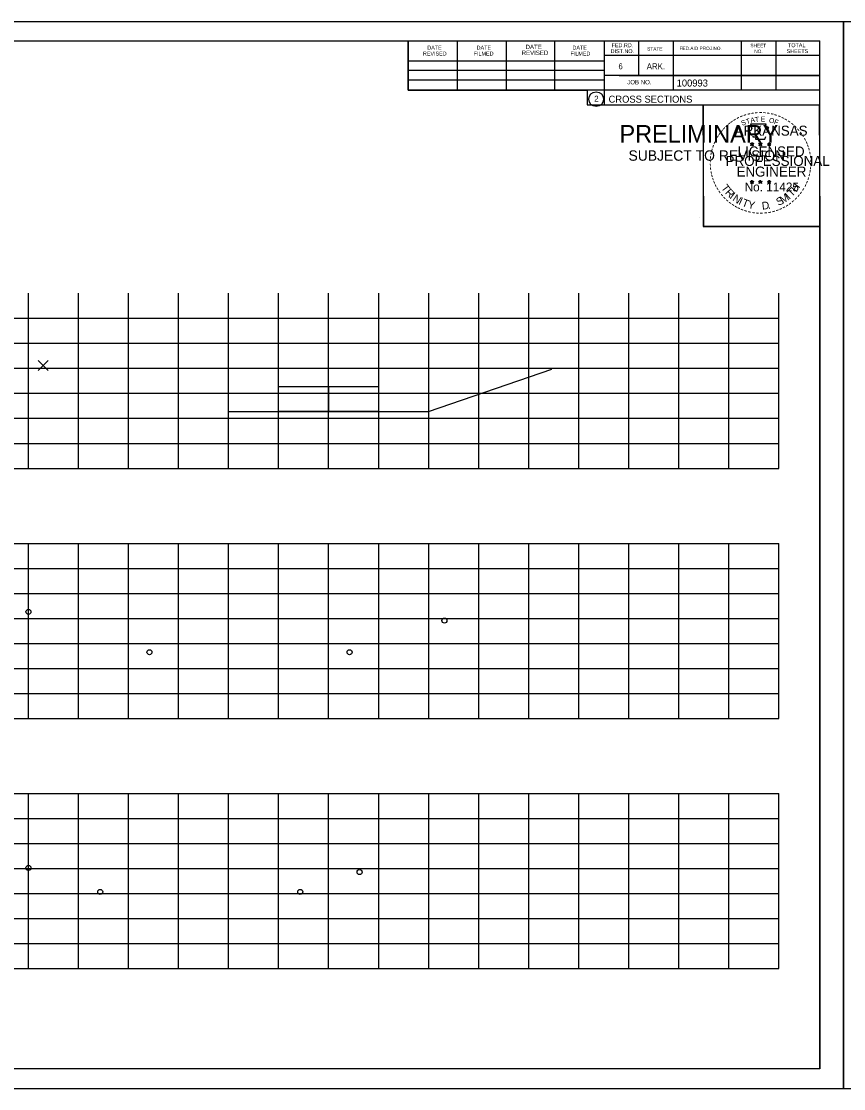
# Model space of a CAD drawing. Extents: x 4667 to 1632277, y -2100 to 724501.
# Drawn here: x 6138.1 to 6302.5, y -1750.4 to -1537.1 of the extents above; entities that cross this region are included whole.
import ezdxf

# ---------------------------------------------------------------- set-up
doc = ezdxf.new("R2010")
doc.units = 0
for name, color, linetype in [('R_Grid', 7, 'Continuous'), ('R_No Plot', 7, 'Continuous'), ('R_Water', 7, 'Continuous')]:
    doc.layers.add(name, color=color, linetype=linetype)

msp = doc.modelspace()

# ---------------------------------------------------------------- linework, layer by layer
at = {"layer": 'R_Grid'}
for p, q in [((6139.52, -1626.44), (6139.52, -1591.44)), ((6149.52, -1626.44), (6149.52, -1591.44)), ((6159.52, -1626.44), (6159.52, -1591.44)), ((6169.52, -1626.44), (6169.52, -1591.44)), ((6179.52, -1626.44), (6179.52, -1591.44)), ((6189.52, -1626.44), (6189.52, -1591.44)), ((6199.52, -1626.44), (6199.52, -1591.44)), ((6209.52, -1626.44), (6209.52, -1591.44)), ((6219.52, -1626.44), (6219.52, -1591.44)), ((6229.52, -1626.44), (6229.52, -1591.44)), ((6239.52, -1626.44), (6239.52, -1591.44)), ((6249.52, -1626.44), (6249.52, -1591.44)), ((6259.52, -1626.44), (6259.52, -1591.44)), ((6269.52, -1626.44), (6269.52, -1591.44)), ((6279.52, -1626.44), (6279.52, -1591.44)), ((6289.52, -1626.44), (6289.52, -1591.44)), ((5989.52, -1596.44), (6289.52, -1596.44)), ((5989.52, -1601.44), (6289.52, -1601.44)), ((5989.52, -1606.44), (6289.52, -1606.44)), ((5989.52, -1611.44), (6289.52, -1611.44)), ((5989.52, -1616.44), (6289.52, -1616.44)), ((5989.52, -1621.44), (6289.52, -1621.44)), ((5989.52, -1626.44), (6289.52, -1626.44)), ((5989.52, -1641.44), (6289.52, -1641.44)), ((6139.52, -1676.44), (6139.52, -1641.44)), ((6149.52, -1676.44), (6149.52, -1641.44)), ((6159.52, -1676.44), (6159.52, -1641.44)), ((6169.52, -1676.44), (6169.52, -1641.44)), ((6179.52, -1676.44), (6179.52, -1641.44)), ((6189.52, -1676.44), (6189.52, -1641.44)), ((6199.52, -1676.44), (6199.52, -1641.44)), ((6209.52, -1676.44), (6209.52, -1641.44)), ((6219.52, -1676.44), (6219.52, -1641.44)), ((6229.52, -1676.44), (6229.52, -1641.44)), ((6239.52, -1676.44), (6239.52, -1641.44)), ((6249.52, -1676.44), (6249.52, -1641.44)), ((6259.52, -1676.44), (6259.52, -1641.44)), ((6269.52, -1676.44), (6269.52, -1641.44)), ((6279.52, -1676.44), (6279.52, -1641.44)), ((6289.52, -1676.44), (6289.52, -1641.44)), ((5989.52, -1646.44), (6289.52, -1646.44)), ((5989.52, -1651.44), (6289.52, -1651.44)), ((5989.52, -1656.44), (6289.52, -1656.44)), ((5989.52, -1661.44), (6289.52, -1661.44)), ((5989.52, -1666.44), (6289.52, -1666.44)), ((5989.52, -1671.44), (6289.52, -1671.44)), ((5989.52, -1676.44), (6289.52, -1676.44)), ((5989.52, -1691.44), (6289.52, -1691.44)), ((6139.52, -1726.44), (6139.52, -1691.44)), ((6149.52, -1726.44), (6149.52, -1691.44)), ((6159.52, -1726.44), (6159.52, -1691.44)), ((6169.52, -1726.44), (6169.52, -1691.44)), ((6179.52, -1726.44), (6179.52, -1691.44)), ((6189.52, -1726.44), (6189.52, -1691.44)), ((6199.52, -1726.44), (6199.52, -1691.44)), ((6209.52, -1726.44), (6209.52, -1691.44)), ((6219.52, -1726.44), (6219.52, -1691.44)), ((6229.52, -1726.44), (6229.52, -1691.44)), ((6239.52, -1726.44), (6239.52, -1691.44)), ((6249.52, -1726.44), (6249.52, -1691.44)), ((6259.52, -1726.44), (6259.52, -1691.44)), ((6269.52, -1726.44), (6269.52, -1691.44)), ((6279.52, -1726.44), (6279.52, -1691.44)), ((6289.52, -1726.44), (6289.52, -1691.44)), ((5989.52, -1696.44), (6289.52, -1696.44)), ((5989.52, -1701.44), (6289.52, -1701.44)), ((5989.52, -1706.44), (6289.52, -1706.44)), ((5989.52, -1711.44), (6289.52, -1711.44)), ((5989.52, -1716.44), (6289.52, -1716.44)), ((5989.52, -1721.44), (6289.52, -1721.44)), ((5989.52, -1726.44), (6289.52, -1726.44))]:
    msp.add_line(p, q, dxfattribs=at)
at = {"layer": 'R_No Plot'}
for p, q in [((5969.12, -1537.09), (6302.46, -1537.09)), ((5981.52, -1540.98), (6297.7, -1540.98)), ((6215.44, -1550.86), (6215.44, -1540.98)), ((6225.3, -1550.86), (6225.3, -1541.18)), ((6235.06, -1550.86), (6235.06, -1541.18)), ((6244.74, -1550.86), (6244.74, -1541.18)), ((6254.6, -1540.98), (6254.6, -1553.78)), ((6261.44, -1540.98), (6261.44, -1547.92)), ((6268.38, -1540.98), (6268.38, -1550.86)), ((6281.96, -1540.98), (6281.96, -1550.86)), ((6288.9, -1540.98), (6288.9, -1550.86)), ((6297.7, -1746.44), (6297.7, -1540.98)), ((6297.7, -1543.92), (6254.6, -1543.92)), ((6297.7, -1543.9), (6297.7, -1543.9)), ((6215.44, -1545), (6254.6, -1545)), ((6215.44, -1546.86), (6254.6, -1546.86)), ((6215.44, -1550.86), (6215.44, -1548.8)), ((6215.44, -1548.8), (6254.6, -1548.8)), ((6297.7, -1547.92), (6254.6, -1547.92)), ((6257.56, -1547.92), (6297.7, -1547.92)), ((6297.7, -1550.86), (6215.44, -1550.86)), ((6254.6, -1553.78), (6297.7, -1553.78)), ((6283.79, -1561.53), (6284.14, -1561.64)), ((6283.79, -1561.53), (6284.04, -1561.57)), ((6283.79, -1561.53), (6284.03, -1561.65)), ((6284.14, -1561.28), (6284.1, -1561.53)), ((6284.14, -1561.64), (6284.14, -1561.28)), ((6284.14, -1561.28), (6284.19, -1561.53)), ((6284.49, -1561.53), (6284.14, -1561.64)), ((6284.49, -1561.53), (6284.2, -1561.58)), ((6284.49, -1561.53), (6284.28, -1561.63)), ((6285.46, -1561.53), (6285.81, -1561.64)), ((6285.46, -1561.53), (6285.71, -1561.57)), ((6285.46, -1561.53), (6285.7, -1561.65)), ((6285.81, -1561.28), (6285.77, -1561.53)), ((6285.81, -1561.64), (6285.81, -1561.28)), ((6285.81, -1561.28), (6285.86, -1561.53)), ((6286.16, -1561.53), (6285.81, -1561.64)), ((6286.16, -1561.53), (6285.87, -1561.58)), ((6286.16, -1561.53), (6285.95, -1561.63)), ((6287.22, -1561.54), (6287.57, -1561.65)), ((6287.22, -1561.54), (6287.48, -1561.59)), ((6287.22, -1561.54), (6287.46, -1561.66)), ((6287.57, -1561.29), (6287.53, -1561.54)), ((6287.57, -1561.65), (6287.57, -1561.29)), ((6287.57, -1561.29), (6287.62, -1561.54)), ((6287.92, -1561.54), (6287.57, -1561.65)), ((6287.92, -1561.54), (6287.63, -1561.59)), ((6287.92, -1561.54), (6287.72, -1561.64)), ((6283.92, -1561.94), (6284.14, -1561.64)), ((6283.92, -1561.94), (6284.05, -1561.69)), ((6283.92, -1561.94), (6284.14, -1561.72)), ((6284.35, -1561.94), (6284.14, -1561.64)), ((6284.35, -1561.94), (6284.14, -1561.72)), ((6284.35, -1561.94), (6284.21, -1561.65)), ((6285.59, -1561.94), (6285.81, -1561.64)), ((6285.59, -1561.94), (6285.72, -1561.69)), ((6285.59, -1561.94), (6285.81, -1561.72)), ((6286.02, -1561.94), (6285.81, -1561.64)), ((6286.02, -1561.94), (6285.81, -1561.72)), ((6286.02, -1561.94), (6285.88, -1561.65)), ((6287.36, -1561.95), (6287.57, -1561.65)), ((6287.36, -1561.95), (6287.48, -1561.71)), ((6287.36, -1561.95), (6287.57, -1561.73)), ((6287.79, -1561.95), (6287.57, -1561.65)), ((6287.79, -1561.95), (6287.57, -1561.74)), ((6287.79, -1561.95), (6287.65, -1561.66)), ((6283.79, -1569.1), (6284.13, -1569.21)), ((6283.79, -1569.1), (6284.04, -1569.15)), ((6283.79, -1569.1), (6284.02, -1569.22)), ((6283.92, -1569.51), (6284.13, -1569.21)), ((6283.92, -1569.51), (6284.04, -1569.27)), ((6283.92, -1569.51), (6284.13, -1569.29)), ((6284.13, -1568.85), (6284.09, -1569.1)), ((6284.13, -1569.21), (6284.13, -1568.85)), ((6284.13, -1568.85), (6284.18, -1569.1)), ((6284.48, -1569.1), (6284.13, -1569.21)), ((6284.35, -1569.51), (6284.13, -1569.21)), ((6284.35, -1569.51), (6284.13, -1569.3)), ((6284.48, -1569.1), (6284.2, -1569.15)), ((6284.35, -1569.51), (6284.21, -1569.22)), ((6284.48, -1569.1), (6284.28, -1569.2)), ((6285.45, -1569.1), (6285.8, -1569.21)), ((6285.45, -1569.1), (6285.71, -1569.15)), ((6285.45, -1569.1), (6285.69, -1569.22)), ((6285.59, -1569.51), (6285.8, -1569.21)), ((6285.59, -1569.51), (6285.71, -1569.27)), ((6285.59, -1569.51), (6285.8, -1569.29)), ((6285.8, -1568.85), (6285.76, -1569.1)), ((6285.8, -1569.21), (6285.8, -1568.85)), ((6285.8, -1568.85), (6285.85, -1569.1)), ((6286.15, -1569.1), (6285.8, -1569.21)), ((6286.02, -1569.51), (6285.8, -1569.21)), ((6286.02, -1569.51), (6285.8, -1569.3)), ((6286.15, -1569.1), (6285.86, -1569.15)), ((6286.02, -1569.51), (6285.88, -1569.22)), ((6286.15, -1569.1), (6285.95, -1569.2)), ((6287.22, -1569.11), (6287.57, -1569.22)), ((6287.22, -1569.11), (6287.47, -1569.16)), ((6287.22, -1569.11), (6287.46, -1569.23)), ((6287.35, -1569.52), (6287.57, -1569.22)), ((6287.35, -1569.52), (6287.48, -1569.28)), ((6287.35, -1569.52), (6287.57, -1569.3)), ((6287.57, -1568.86), (6287.53, -1569.11)), ((6287.57, -1569.22), (6287.57, -1568.86)), ((6287.57, -1568.86), (6287.62, -1569.11)), ((6287.92, -1569.11), (6287.57, -1569.22)), ((6287.78, -1569.52), (6287.57, -1569.22)), ((6287.78, -1569.52), (6287.57, -1569.31)), ((6287.92, -1569.11), (6287.63, -1569.16)), ((6287.78, -1569.52), (6287.65, -1569.23)), ((6287.92, -1569.11), (6287.71, -1569.21)), ((6273.74, -1576.24), (6273.74, -1576.24)), ((6297.7, -1746.44), (5981.52, -1746.44)), ((5969.12, -1750.42), (6302.46, -1750.42))]:
    msp.add_line(p, q, dxfattribs=at)
for points in [[(5969.12, -1537.09), (6302.46, -1537.09), (6302.46, -1750.43), (5969.12, -1750.43)], [(6302.46, -1537.09), (6635.8, -1537.09), (6635.8, -1750.43), (6302.46, -1750.43)], [(6215.44, -1540.98), (6215.44, -1550.86), (6251.18, -1550.86), (6251.18, -1553.78), (6274.38, -1553.78), (6274.38, -1578.12), (6297.7, -1578.12), (6297.7, -1746.44), (5981.52, -1746.44), (5981.52, -1540.98)], [(6274.38, -1553.78), (6297.58, -1553.78), (6297.7, -1578.12), (6274.5, -1578.12)]]:
    msp.add_lwpolyline(points, close=True, dxfattribs=at)
for points in [[(6283.83, -1557.65), (6284.1, -1558.48)], [(6287.34, -1558.57), (6287.48, -1558.29), (6286.8, -1558.31), (6286.95, -1557.65), (6283.83, -1557.65)], [(6284.14, -1561.28), (6284.35, -1561.94), (6283.79, -1561.53), (6284.49, -1561.53), (6283.92, -1561.94), (6284.14, -1561.28)], [(6284.32, -1560.07), (6284.32, -1560.16), (6284.89, -1560.18), (6284.83, -1560.65), (6286.7, -1560.65), (6286.9, -1560.12)], [(6285.81, -1561.28), (6286.02, -1561.94), (6285.46, -1561.53), (6286.16, -1561.53), (6285.59, -1561.94), (6285.81, -1561.28)], [(6287.57, -1561.29), (6287.79, -1561.95), (6287.22, -1561.54), (6287.92, -1561.54), (6287.36, -1561.95), (6287.57, -1561.29)], [(6284.13, -1568.85), (6284.35, -1569.51), (6283.79, -1569.1), (6284.48, -1569.1), (6283.92, -1569.51), (6284.13, -1568.85)], [(6285.8, -1568.85), (6286.02, -1569.51), (6285.45, -1569.1), (6286.15, -1569.1), (6285.59, -1569.51), (6285.8, -1568.85)], [(6287.57, -1568.86), (6287.78, -1569.52), (6287.22, -1569.11), (6287.92, -1569.11), (6287.35, -1569.52), (6287.57, -1568.86)], [(6142.44, -1605.88), (6141.44, -1604.88), (6142.44, -1605.88), (6141.44, -1606.88), (6142.44, -1605.88), (6143.44, -1606.88), (6142.44, -1605.88), (6143.44, -1604.88)]]:
    msp.add_lwpolyline(points, dxfattribs=at)
for centre, radius in [((6252.99, -1552.65), 1.47), ((6284.14, -1561.64), 0.172), ((6284.14, -1561.64), 0.145), ((6284.14, -1561.64), 0.116), ((6284.14, -1561.64), 0.0991), ((6284.14, -1561.64), 0.0747), ((6284.14, -1561.64), 0.0495), ((6284.14, -1561.64), 0.0296), ((6285.81, -1561.64), 0.172), ((6285.81, -1561.64), 0.145), ((6285.81, -1561.64), 0.116), ((6285.81, -1561.64), 0.0991), ((6285.81, -1561.64), 0.0747), ((6285.81, -1561.64), 0.0495), ((6285.81, -1561.64), 0.0296), ((6287.57, -1561.65), 0.172), ((6287.57, -1561.65), 0.145), ((6287.57, -1561.65), 0.116), ((6287.57, -1561.65), 0.0991), ((6287.57, -1561.65), 0.0747), ((6287.57, -1561.65), 0.0495), ((6287.57, -1561.65), 0.0296), ((6284.13, -1569.21), 0.172), ((6284.13, -1569.21), 0.145), ((6284.13, -1569.21), 0.116), ((6284.13, -1569.21), 0.0991), ((6284.13, -1569.21), 0.0747), ((6284.13, -1569.21), 0.0495), ((6284.13, -1569.21), 0.0296), ((6285.8, -1569.21), 0.172), ((6285.8, -1569.21), 0.145), ((6285.8, -1569.21), 0.116), ((6285.8, -1569.21), 0.0991), ((6285.8, -1569.21), 0.0747), ((6285.8, -1569.21), 0.0495), ((6285.8, -1569.21), 0.0296), ((6287.57, -1569.22), 0.172), ((6287.57, -1569.22), 0.145), ((6287.57, -1569.22), 0.116), ((6287.57, -1569.22), 0.0991), ((6287.57, -1569.22), 0.0747), ((6287.57, -1569.22), 0.0495), ((6287.57, -1569.22), 0.0296), ((6139.52, -1655.13), 0.5), ((6222.65, -1656.87), 0.5), ((6163.7, -1663.19), 0.5), ((6203.7, -1663.19), 0.5), ((6139.52, -1706.31), 0.5), ((6205.71, -1707.14), 0.5), ((6153.85, -1711.09), 0.5), ((6193.85, -1711.09), 0.5)]:
    msp.add_circle(centre, radius, dxfattribs=at)
at = {"layer": 'R_Water'}
msp.add_lwpolyline([(6179.51, -1615.06), (6219.51, -1615.06), (6244.1, -1606.62)], dxfattribs=at)
for points in [[(6189.51, -1615.06), (6189.51, -1610.06), (6199.51, -1610.06), (6199.51, -1615.06)], [(6199.51, -1615.06), (6199.51, -1610.06), (6209.51, -1610.06), (6209.51, -1615.06)]]:
    msp.add_lwpolyline(points, close=True, dxfattribs=at)

# ---------------------------------------------------------------- texts
at = {"layer": 'R_No Plot'}
for s, height, rotation, p in [('DATE', 0.782, 360, (6219.24, -1542.74)), ('DATE', 0.782, 360, (6229.1, -1542.74)), ('DATE', 0.879, 360, (6238.88, -1542.64)), ('DATE', 0.782, 360, (6248.26, -1542.74)), ('FED.RD.', 0.782, 360, (6256.08, -1542.26)), ('STATE', 0.684, 360, (6263.2, -1542.94)), ('FED.AID PROJ.NO.', 0.684, 360, (6269.66, -1542.84)), ('SHEET', 0.684, 360, (6283.82, -1542.26)), ('TOTAL', 0.782, 360, (6291.34, -1542.26)), ('REVISED', 0.782, 360, (6218.36, -1543.92)), ('FILMED', 0.782, 360, (6228.52, -1543.92)), ('REVISED', 0.879, 360, (6238.1, -1543.82)), ('FILMED', 0.782, 360, (6247.86, -1543.92)), ('DIST.NO.', 0.782, 360, (6255.88, -1543.44)), ('NO.', 0.684, 360, (6284.6, -1543.44)), ('SHEETS', 0.782, 360, (6291.06, -1543.44)), ('6', 1.17, 360, (6257.44, -1546.66)), ('ARK.', 1.172, 360, (6263.1, -1546.66)), ('JOB NO.', 0.879, 360, (6259.2, -1549.68)), ('100993', 1.4, 360, (6269.08, -1550.12)), ('2', 1.17, 360, (6252.61, -1553.14)), ('CROSS SECTIONS', 1.4, 360, (6255.47, -1553.35)), ('-', 1.6, 0.1862, (6285.51, -1555.94)), ('-', 1.6, 38.9507, (6279.66, -1558.25)), ('-', 1.6, 36.2317, (6280.14, -1557.88)), ('-', 1.6, 34.0636, (6280.71, -1557.48)), ('-', 1.6, 28.7918, (6281.31, -1557.11)), ('-', 1.6, 24.3072, (6281.94, -1556.79)), ('S', 1, 21.594, (6282.18, -1557.97)), ('-', 1.6, 19.1761, (6282.58, -1556.52)), ('T', 1, 16.4036, (6283.1, -1557.64)), ('-', 1.6, 13.6301, (6283.33, -1556.28)), ('A', 1, 11.2132, (6283.92, -1557.39)), ('-', 1.6, 10.2193, (6284.01, -1556.12)), ('T', 1, 6.0228, (6284.77, -1557.23)), ('-', 1.6, 5.8968, (6284.73, -1556.01)), ('E', 1, 0.8323, (6285.88, -1557.12)), ('-', 1.6, 357.743, (6286.23, -1555.95)), ('-', 1.6, 352.1617, (6286.97, -1556.01)), ('O', 1, 350.4515, (6287.48, -1557.33)), ('-', 1.6, 347.2049, (6287.69, -1556.12)), ('F', 1, 340.0707, (6288.44, -1557.55)), ('-', 1.6, 342.3362, (6288.33, -1556.28)), ('-', 1.6, 337.8551, (6289.06, -1556.5)), ('-', 1.6, 334.1211, (6289.69, -1556.77)), ('-', 1.6, 329.6409, (6290.27, -1557.05)), ('-', 1.6, 325.8627, (6290.92, -1557.42)), ('-', 1.6, 320.5297, (6291.53, -1557.84)), ('PRELIMINARY', 3.5, 360, (6257.66, -1561.32)), ('DWB', 0.01, 360, (6258.4, -1559.47)), ('-', 1.6, 54.2325, (6277.96, -1560.2)), ('-', 1.6, 50.6142, (6278.38, -1559.63)), ('-', 1.6, 48.423, (6278.78, -1559.15)), ('-', 1.6, 42.9622, (6279.23, -1558.67)), ('ARKANSAS', 2, 360, (6280.68, -1559.94)), ('-', 1.6, 315.5786, (6292.12, -1558.33)), ('-', 1.6, 309.8797, (6292.69, -1558.88)), ('-', 1.6, 306.6522, (6293.22, -1559.48)), ('-', 1.6, 67.7743, (6277.07, -1561.95)), ('-', 1.6, 62.8713, (6277.32, -1561.34)), ('-', 1.6, 58.0706, (6277.64, -1560.73)), ('-', 1.4, 303.6753, (6293.7, -1560.05)), ('-', 1.6, 299.6684, (6294.02, -1560.66)), ('-', 1.6, 294.6628, (6294.35, -1561.27)), ('SUBJECT TO REVISION', 2.0751, 360, (6259.46, -1564.95)), ('-', 1.6, 81.2013, (6276.52, -1564.01)), ('-', 1.6, 75.461, (6276.65, -1563.3)), ('-', 1.6, 72.3945, (6276.85, -1562.58)), ('LICENSED', 2, 360, (6281.28, -1564.09)), ('DWB', 0.01, 360, (6284.13, -1561.65)), ('DWB', 0.01, 360, (6285.8, -1561.65)), ('DWB', 0.01, 360, (6287.56, -1561.66)), ('-', 1.6, 290.5728, (6294.6, -1561.85)), ('-', 1.6, 285.1233, (6294.84, -1562.43)), ('-', 1.6, 280.5493, (6295.04, -1563.17)), ('-', 1.6, 94.1959, (6276.45, -1566.13)), ('-', 1.6, 89.0622, (6276.42, -1565.4)), ('-', 1.6, 85.1863, (6276.44, -1564.7)), ('PROFESSIONAL', 2, 360, (6278.86, -1565.99)), ('-', 1.6, 276.5962, (6295.2, -1563.94)), ('-', 1.6, 274.3301, (6295.26, -1564.66)), ('-', 1.6, 269.9407, (6295.29, -1565.29)), ('-', 1.6, 98.9479, (6276.52, -1566.79)), ('-', 1.6, 101.7149, (6276.66, -1567.53)), ('-', 1.6, 105.4578, (6276.82, -1568.12)), ('ENGINEER', 2, 360, (6281.04, -1568.12)), ('-', 1.6, 255.7626, (6295.09, -1567.29)), ('-', 1.6, 260.9953, (6295.2, -1566.61)), ('-', 1.6, 263.5172, (6295.28, -1565.96)), ('-', 1.6, 109.0874, (6277.04, -1568.75)), ('-', 1.6, 114.0643, (6277.29, -1569.35)), ('-', 1.6, 115.7289, (6277.59, -1569.97)), ('T', 1.54, 306.0406, (6277.89, -1570.38)), ('No. 11425', 1.757, 360, (6282.67, -1571.07)), ('DWB', 0.01, 360, (6284.12, -1569.22)), ('DWB', 0.01, 360, (6285.79, -1569.22)), ('DWB', 0.01, 360, (6287.56, -1569.23)), ('H', 1.54, 54.6088, (6293.01, -1571.34)), ('-', 1.6, 244.6197, (6294.43, -1569.31)), ('-', 1.6, 247.8887, (6294.69, -1568.68)), ('-', 1.6, 252.8681, (6294.91, -1568.01)), ('-', 1.6, 120.4471, (6277.95, -1570.55)), ('-', 1.6, 125.8934, (6278.35, -1571.11)), ('-', 1.6, 130.7181, (6278.82, -1571.67)), ('-', 1.6, 134.2238, (6279.33, -1572.21)), ('R', 1.54, 314.005, (6278.66, -1571.42)), ('I', 1.54, 321.9694, (6279.56, -1572.35)), ('N', 1.54, 326.5002, (6280.12, -1572.83)), ('I', 1.54, 335.3603, (6281.33, -1573.61)), ('S', 1.54, 26.9312, (6289.44, -1574.01)), ('M', 1.54, 32.6563, (6290.28, -1573.61)), ('I', 1.54, 42.1136, (6291.56, -1572.76)), ('T', 1.54, 46.6444, (6292.12, -1572.28)), ('-', 1.6, 225.7653, (6292.72, -1571.84)), ('-', 1.6, 231.2538, (6293.2, -1571.28)), ('-', 1.6, 233.8452, (6293.63, -1570.71)), ('-', 1.6, 239.0712, (6294.03, -1570.06)), ('-', 1.6, 138.9338, (6279.86, -1572.68)), ('-', 1.6, 144.6463, (6280.41, -1573.08)), ('-', 1.6, 148.0898, (6280.98, -1573.45)), ('-', 1.6, 151.5704, (6281.55, -1573.78)), ('-', 1.6, 154.6002, (6282.08, -1574.02)), ('T', 1.54, 339.8912, (6281.99, -1573.94)), ('Y', 1.54, 347.8556, (6283.21, -1574.39)), ('D', 1.54, 6.3969, (6286.19, -1574.74)), ('.', 1.54, 13.7642, (6287.39, -1574.62)), ('-', 1.6, 204.2516, (6289.94, -1573.88)), ('-', 1.6, 207.3568, (6290.56, -1573.56)), ('-', 1.6, 212.2491, (6291.12, -1573.21)), ('-', 1.6, 215.7363, (6291.65, -1572.83)), ('-', 1.6, 221.0851, (6292.2, -1572.35)), ('-', 1.6, 158.5612, (6282.7, -1574.28)), ('-', 1.6, 162.7983, (6283.39, -1574.49)), ('-', 1.6, 167.5555, (6284.1, -1574.66)), ('-', 1.6, 173.1155, (6284.87, -1574.77)), ('-', 1.6, 176.5183, (6285.62, -1574.82)), ('-', 1.6, 181.5918, (6286.37, -1574.8)), ('-', 1.6, 185.8167, (6287.18, -1574.72)), ('-', 1.6, 191.2858, (6287.91, -1574.59)), ('-', 1.6, 195.4743, (6288.64, -1574.39)), ('-', 1.6, 200.7184, (6289.32, -1574.15))]:
    msp.add_text(s, height=height, rotation=rotation, dxfattribs=at).set_placement(p)

doc.saveas('drawing.dxf')
